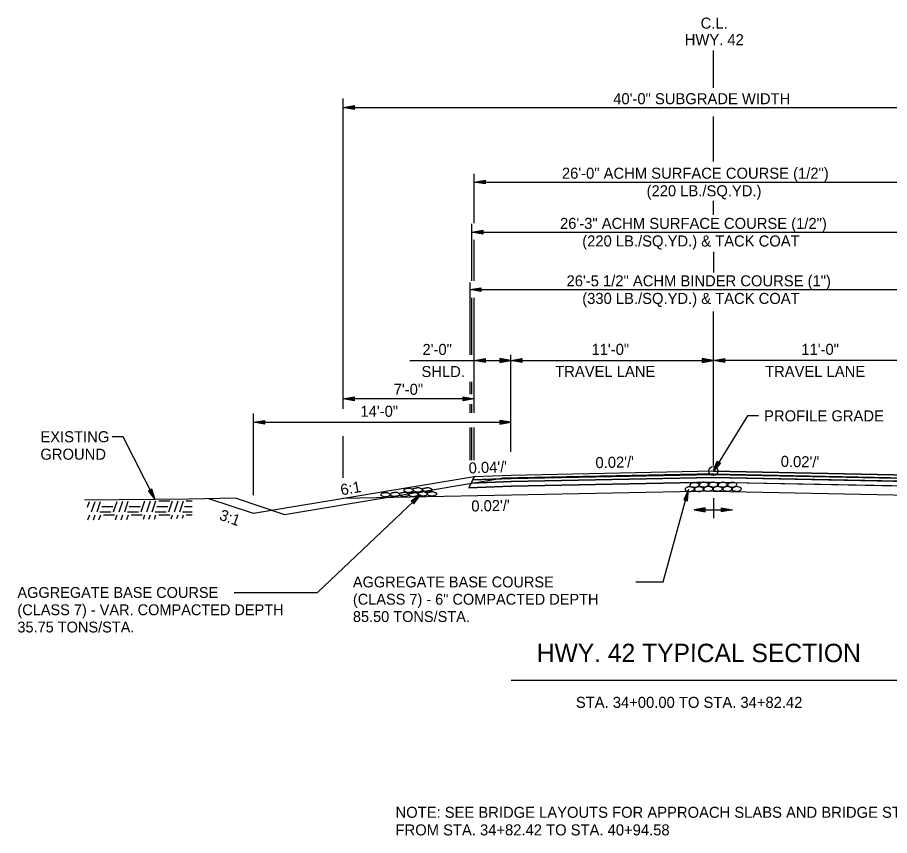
# Model space of a CAD drawing. Extents: x 1461570 to 1461697, y 1686711 to 1686957.
# Drawn here: x 1461574.47 to 1461621.86, y 1686717.78 to 1686762.26 of the extents above; entities that cross this region are included whole.
import ezdxf

# ---------------------------------------------------------------- set-up
doc = ezdxf.new("R2010")
doc.units = 0
for name, color, linetype in [('1', 7, 'Continuous'), ('10', 7, 'Continuous'), ('19', 7, 'Continuous'), ('20', 7, 'Continuous'), ('3', 7, 'Continuous'), ('42', 7, 'Continuous'), ('Default', 7, 'Continuous'), ('Level 1', 7, 'Continuous'), ('Level 9', 7, 'Continuous'), ('R_Draft', 7, 'Continuous'), ('R_Prop Surface', 7, 'Continuous')]:
    doc.layers.add(name, color=color, linetype=linetype)

# ---------------------------------------------------------------- blocks, each defined once
blk = doc.blocks.new('ROCKS')
at = {"layer": '1'}
blk.add_spline([(0.013, 0.06), (0.053, 0.053), (0.107, 0.033), (0.133, 0.013), (0.133, -0.007), (0.12, -0.033), (0.107, -0.04), (0.073, -0.053), (0.033, -0.067), (0.013, -0.067), (-0.02, -0.06), (-0.06, -0.053), (-0.087, -0.047), (-0.113, -0.02), (-0.113, -0.007), (-0.107, 0.02), (-0.087, 0.033), (-0.067, 0.047), (-0.033, 0.053), (-0.02, 0.06), (0.013, 0.06)], degree=3, dxfattribs=at)

msp = doc.modelspace()

# ---------------------------------------------------------------- linework, layer by layer
at = {"layer": '19'}
for p, q in [((1461592.17, 1686741.519), (1461592.77, 1686741.624)), ((1461592.77, 1686741.414), (1461592.17, 1686741.519)), ((1461592.33, 1686741.534), (1461592.77, 1686741.569)), ((1461592.77, 1686741.464), (1461592.33, 1686741.504)), ((1461592.77, 1686741.624), (1461592.77, 1686741.414)), ((1461598.685, 1686741.413), (1461598.685, 1686741.623)), ((1461598.685, 1686741.623), (1461599.285, 1686741.519)), ((1461598.685, 1686741.568), (1461599.125, 1686741.534)), ((1461599.285, 1686741.519), (1461598.685, 1686741.413)), ((1461599.125, 1686741.504), (1461598.685, 1686741.463)), ((1461612.275, 1686737.57), (1461612.498, 1686738.137)), ((1461612.676, 1686738.027), (1461612.275, 1686737.57)), ((1461612.348, 1686737.711), (1461612.541, 1686738.104)), ((1461612.635, 1686738.048), (1461612.371, 1686737.7)), ((1461612.498, 1686738.137), (1461612.676, 1686738.027)), ((1461612.285, 1686737.582), (1461601.285, 1686737.362)), ((1461612.285, 1686737.582), (1461601.285, 1686737.362)), ((1461612.285, 1686737.416), (1461601.29, 1686737.196)), ((1461612.285, 1686737.582), (1461623.285, 1686737.362)), ((1461623.285, 1686737.362), (1461612.285, 1686737.582)), ((1461612.285, 1686737.582), (1461623.285, 1686737.362)), ((1461612.285, 1686737.416), (1461622.202, 1686737.217)), ((1461612.285, 1686737.416), (1461612.285, 1686737.416)), ((1461612.285, 1686737.416), (1461612.285, 1686737.416)), ((1461612.285, 1686737.416), (1461623.28, 1686737.196)), ((1461599.285, 1686737.282), (1461587.285, 1686735.282)), ((1461599.285, 1686737.282), (1461598.991, 1686736.687)), ((1461599.117, 1686736.942), (1461598.991, 1686736.687)), ((1461599.201, 1686737.112), (1461599.117, 1686736.942)), ((1461599.285, 1686737.282), (1461599.201, 1686737.112)), ((1461612.285, 1686737.249), (1461601.295, 1686737.029)), ((1461612.285, 1686736.999), (1461601.303, 1686736.779)), ((1461612.285, 1686737.249), (1461612.285, 1686737.249)), ((1461612.285, 1686737.249), (1461612.285, 1686737.249)), ((1461612.285, 1686737.249), (1461623.275, 1686737.029)), ((1461612.285, 1686736.999), (1461612.285, 1686736.999)), ((1461612.285, 1686736.999), (1461623.268, 1686736.779)), ((1461612.285, 1686736.499), (1461592.17, 1686736.097)), ((1461609.564, 1686731.575), (1461610.941, 1686736.585)), ((1461610.941, 1686736.585), (1461610.685, 1686736.032)), ((1461610.887, 1686735.98), (1461610.941, 1686736.585)), ((1461612.285, 1686736.499), (1461632.401, 1686736.097)), ((1461587.285, 1686735.282), (1461584.872, 1686736.087)), ((1461590.775, 1686730.998), (1461596.374, 1686736.296)), ((1461596.375, 1686736.3), (1461595.867, 1686735.965)), ((1461596.251, 1686736.2), (1461595.905, 1686735.928)), ((1461595.977, 1686735.85), (1461596.271, 1686736.179)), ((1461596.011, 1686735.814), (1461596.375, 1686736.3)), ((1461610.685, 1686736.032), (1461610.887, 1686735.98)), ((1461610.888, 1686736.434), (1461610.737, 1686736.022)), ((1461610.839, 1686735.993), (1461610.915, 1686736.427)), ((1461595.867, 1686735.965), (1461596.011, 1686735.814)), ((1461608.066, 1686731.575), (1461609.564, 1686731.575)), ((1461586.24, 1686730.998), (1461590.775, 1686730.998))]:
    msp.add_line(p, q, dxfattribs=at)
for points in [[(1461614.743, 1686740.596), (1461614.143, 1686740.596), (1461612.275, 1686737.571)], [(1461612.285, 1686737.582), (1461601.285, 1686737.362)], [(1461612.285, 1686737.416), (1461601.29, 1686737.196)], [(1461602.202, 1686737.214), (1461612.285, 1686737.416)], [(1461612.285, 1686737.249), (1461623.275, 1686737.029), (1461625.454, 1686736.942), (1461625.37, 1686737.112), (1461623.28, 1686737.196), (1461612.285, 1686737.416)], [(1461612.285, 1686737.416), (1461612.285, 1686737.416)], [(1461598.991, 1686736.687), (1461601.303, 1686736.779), (1461612.285, 1686736.999)], [(1461599.117, 1686736.942), (1461601.295, 1686737.029), (1461612.285, 1686737.249)], [(1461612.285, 1686737.249), (1461601.295, 1686737.029), (1461599.117, 1686736.942)], [(1461599.201, 1686737.112), (1461601.29, 1686737.196), (1461601.29, 1686737.196)], [(1461601.29, 1686737.196), (1461599.201, 1686737.112)], [(1461601.285, 1686737.362), (1461599.285, 1686737.282)], [(1461601.29, 1686737.196), (1461602.202, 1686737.214)], [(1461612.285, 1686737.249), (1461612.285, 1686737.249)], [(1461612.285, 1686737.249), (1461612.285, 1686737.249)], [(1461612.285, 1686737.249), (1461612.285, 1686737.249), (1461612.285, 1686737.249)], [(1461612.285, 1686736.999), (1461623.268, 1686736.779), (1461625.58, 1686736.687), (1461625.454, 1686736.942), (1461623.275, 1686737.029), (1461612.285, 1686737.249)]]:
    msp.add_lwpolyline(points, dxfattribs=at)
at = {"layer": '20'}
for p, q in [((1461592.17, 1686740.986), (1461592.17, 1686757.853)), ((1461592.17, 1686757.365), (1461592.77, 1686757.47)), ((1461592.17, 1686757.365), (1461632.401, 1686757.365)), ((1461592.77, 1686757.26), (1461592.17, 1686757.365)), ((1461592.33, 1686757.38), (1461592.77, 1686757.415)), ((1461592.77, 1686757.31), (1461592.33, 1686757.35)), ((1461592.77, 1686757.47), (1461592.77, 1686757.26)), ((1461592.17, 1686750.799), (1461592.17, 1686756.936)), ((1461599.285, 1686751.078), (1461599.285, 1686753.762)), ((1461599.285, 1686753.31), (1461599.885, 1686753.415)), ((1461599.285, 1686753.31), (1461625.285, 1686753.31)), ((1461599.885, 1686753.205), (1461599.285, 1686753.31)), ((1461599.445, 1686753.325), (1461599.885, 1686753.36)), ((1461599.885, 1686753.255), (1461599.445, 1686753.295)), ((1461599.885, 1686753.415), (1461599.885, 1686753.205)), ((1461599.159, 1686747.93), (1461599.159, 1686751.035)), ((1461599.159, 1686750.582), (1461599.759, 1686750.687)), ((1461599.759, 1686750.687), (1461599.759, 1686750.477)), ((1461599.159, 1686750.582), (1461625.412, 1686750.582)), ((1461599.759, 1686750.477), (1461599.159, 1686750.582)), ((1461599.319, 1686750.597), (1461599.759, 1686750.632)), ((1461599.759, 1686750.527), (1461599.319, 1686750.567)), ((1461599.285, 1686747.93), (1461599.285, 1686750.162)), ((1461599.054, 1686747.845), (1461599.054, 1686743.909)), ((1461599.054, 1686747.459), (1461599.654, 1686747.564)), ((1461599.054, 1686747.459), (1461625.517, 1686747.459)), ((1461599.654, 1686747.354), (1461599.054, 1686747.459)), ((1461599.214, 1686747.474), (1461599.654, 1686747.509)), ((1461599.654, 1686747.404), (1461599.214, 1686747.444)), ((1461599.654, 1686747.564), (1461599.654, 1686747.354)), ((1461599.159, 1686743.909), (1461599.159, 1686747.013)), ((1461599.285, 1686743.909), (1461599.285, 1686747.013)), ((1461599.285, 1686740.759), (1461599.285, 1686743.931)), ((1461599.285, 1686743.607), (1461599.885, 1686743.712)), ((1461599.885, 1686743.502), (1461599.285, 1686743.607)), ((1461599.445, 1686743.622), (1461599.885, 1686743.657)), ((1461599.885, 1686743.552), (1461599.445, 1686743.592)), ((1461599.885, 1686743.712), (1461599.885, 1686743.502)), ((1461600.685, 1686743.712), (1461600.685, 1686743.502)), ((1461601.285, 1686743.607), (1461600.685, 1686743.712)), ((1461601.125, 1686743.622), (1461600.685, 1686743.657)), ((1461600.685, 1686743.502), (1461601.285, 1686743.607)), ((1461600.685, 1686743.552), (1461601.125, 1686743.592)), ((1461601.285, 1686738.638), (1461601.285, 1686743.906)), ((1461601.285, 1686743.607), (1461601.885, 1686743.712)), ((1461601.885, 1686743.502), (1461601.285, 1686743.607)), ((1461601.445, 1686743.622), (1461601.885, 1686743.657)), ((1461601.885, 1686743.552), (1461601.445, 1686743.592)), ((1461601.885, 1686743.712), (1461601.885, 1686743.502)), ((1461611.685, 1686743.713), (1461611.685, 1686743.503)), ((1461612.285, 1686743.608), (1461611.685, 1686743.713)), ((1461612.125, 1686743.623), (1461611.685, 1686743.658)), ((1461611.685, 1686743.503), (1461612.285, 1686743.608)), ((1461611.685, 1686743.553), (1461612.125, 1686743.593)), ((1461612.285, 1686743.608), (1461612.885, 1686743.713)), ((1461612.885, 1686743.503), (1461612.285, 1686743.608)), ((1461612.445, 1686743.623), (1461612.885, 1686743.658)), ((1461612.885, 1686743.553), (1461612.445, 1686743.593)), ((1461612.885, 1686743.713), (1461612.885, 1686743.503)), ((1461599.054, 1686742.455), (1461599.054, 1686741.775)), ((1461599.159, 1686741.775), (1461599.159, 1686742.455)), ((1461599.054, 1686741.238), (1461599.054, 1686740.759)), ((1461599.159, 1686740.759), (1461599.159, 1686741.238)), ((1461587.285, 1686736.283), (1461587.285, 1686740.719)), ((1461587.285, 1686740.246), (1461587.885, 1686740.352)), ((1461587.885, 1686740.142), (1461587.285, 1686740.246)), ((1461587.445, 1686740.262), (1461587.885, 1686740.297)), ((1461587.885, 1686740.352), (1461587.885, 1686740.142)), ((1461600.685, 1686740.352), (1461600.685, 1686740.142)), ((1461601.285, 1686740.246), (1461600.685, 1686740.352)), ((1461601.125, 1686740.262), (1461600.685, 1686740.297)), ((1461600.685, 1686740.142), (1461601.285, 1686740.246)), ((1461587.885, 1686740.192), (1461587.445, 1686740.232)), ((1461599.054, 1686739.969), (1461599.054, 1686738.191)), ((1461599.159, 1686738.191), (1461599.159, 1686739.969)), ((1461599.285, 1686738.191), (1461599.285, 1686739.969)), ((1461600.685, 1686740.192), (1461601.125, 1686740.232)), ((1461592.17, 1686737.224), (1461592.17, 1686739.484)), ((1461581.771, 1686736.606), (1461581.583, 1686736.511)), ((1461581.583, 1686736.511), (1461581.947, 1686736.023)), ((1461581.628, 1686736.534), (1461581.862, 1686736.159)), ((1461581.888, 1686736.172), (1461581.722, 1686736.581)), ((1461581.947, 1686736.023), (1461581.771, 1686736.606))]:
    msp.add_line(p, q, dxfattribs=at)
msp.add_lwpolyline([(1461581.947, 1686736.023), (1461580.217, 1686739.462), (1461579.617, 1686739.462)], dxfattribs=at)
at = {"layer": '3'}
msp.add_line((1461601.3, 1686726.22), (1461623.3, 1686726.22), dxfattribs=at)
at = {"layer": '42'}
for p, q in [((1461612.285, 1686758.427), (1461612.285, 1686760.458)), ((1461612.285, 1686754.424), (1461612.285, 1686756.866)), ((1461612.285, 1686751.526), (1461612.285, 1686752.291)), ((1461612.285, 1686749.511), (1461612.285, 1686748.39)), ((1461612.285, 1686737.903), (1461612.285, 1686746.266)), ((1461595.781, 1686743.607), (1461600.291, 1686743.607)), ((1461600.285, 1686743.607), (1461612.285, 1686743.608)), ((1461624.285, 1686743.606), (1461612.285, 1686743.607)), ((1461587.285, 1686740.246), (1461601.285, 1686740.246)), ((1461581.193, 1686735.374), (1461581.393, 1686735.974)), ((1461581.493, 1686735.374), (1461581.693, 1686735.974)), ((1461581.793, 1686735.374), (1461581.993, 1686735.974)), ((1461582.143, 1686735.974), (1461582.743, 1686735.974)), ((1461582.693, 1686735.374), (1461582.893, 1686735.974)), ((1461582.993, 1686735.374), (1461583.193, 1686735.974)), ((1461583.293, 1686735.374), (1461583.493, 1686735.974)), ((1461583.643, 1686735.974), (1461583.953, 1686735.974)), ((1461612.285, 1686736.119), (1461612.285, 1686735.032)), ((1461578.279, 1686735.634), (1461578.381, 1686735.94)), ((1461578.493, 1686735.374), (1461578.681, 1686735.938)), ((1461578.793, 1686735.374), (1461578.98, 1686735.936)), ((1461579.043, 1686735.674), (1461579.643, 1686735.674)), ((1461579.693, 1686735.374), (1461579.883, 1686735.945)), ((1461579.993, 1686735.374), (1461580.185, 1686735.952)), ((1461580.293, 1686735.374), (1461580.487, 1686735.958)), ((1461580.543, 1686735.674), (1461581.143, 1686735.674)), ((1461582.043, 1686735.674), (1461582.643, 1686735.674)), ((1461583.543, 1686735.674), (1461583.953, 1686735.674)), ((1461611.838, 1686735.589), (1461611.238, 1686735.484)), ((1461611.838, 1686735.534), (1461611.398, 1686735.499)), ((1461611.838, 1686735.379), (1461611.838, 1686735.589)), ((1461612.733, 1686735.379), (1461612.733, 1686735.589)), ((1461612.733, 1686735.589), (1461613.333, 1686735.484)), ((1461612.733, 1686735.534), (1461613.173, 1686735.499)), ((1461578.298, 1686734.941), (1461578.393, 1686735.224)), ((1461578.598, 1686734.939), (1461578.693, 1686735.224)), ((1461578.897, 1686734.936), (1461578.993, 1686735.224)), ((1461578.943, 1686735.374), (1461579.543, 1686735.374)), ((1461579.143, 1686735.224), (1461579.743, 1686735.224)), ((1461579.799, 1686734.944), (1461579.893, 1686735.224)), ((1461580.101, 1686734.95), (1461580.193, 1686735.224)), ((1461580.403, 1686734.956), (1461580.493, 1686735.224)), ((1461580.443, 1686735.374), (1461581.043, 1686735.374)), ((1461580.643, 1686735.224), (1461581.193, 1686735.224)), ((1461581.193, 1686735.224), (1461581.243, 1686735.224)), ((1461581.31, 1686734.975), (1461581.393, 1686735.224)), ((1461581.612, 1686734.981), (1461581.693, 1686735.224)), ((1461581.914, 1686734.987), (1461581.993, 1686735.224)), ((1461581.943, 1686735.374), (1461582.543, 1686735.374)), ((1461582.143, 1686735.224), (1461582.743, 1686735.224)), ((1461582.82, 1686735.006), (1461582.893, 1686735.224)), ((1461583.123, 1686735.016), (1461583.193, 1686735.224)), ((1461583.429, 1686735.034), (1461583.493, 1686735.224)), ((1461583.443, 1686735.374), (1461583.953, 1686735.374)), ((1461583.643, 1686735.224), (1461583.953, 1686735.224)), ((1461611.238, 1686735.484), (1461611.838, 1686735.379)), ((1461611.238, 1686735.484), (1461613.333, 1686735.484)), ((1461611.398, 1686735.469), (1461611.838, 1686735.429)), ((1461613.333, 1686735.484), (1461612.733, 1686735.379)), ((1461613.173, 1686735.469), (1461612.733, 1686735.429))]:
    msp.add_line(p, q, dxfattribs=at)
msp.add_circle((1461612.284, 1686737.601), 0.25, dxfattribs=at)
at = {"layer": 'Level 9'}
msp.add_line((1461599.285, 1686741.519), (1461592.17, 1686741.519), dxfattribs=at)
at = {"layer": 'R_Draft'}
for p, q in [((1461612.285, 1686737.437), (1461600.785, 1686737.207)), ((1461612.285, 1686737.437), (1461622.785, 1686737.227)), ((1461588.984, 1686735.24), (1461600.785, 1686737.207)), ((1461586.351, 1686736.117), (1461588.984, 1686735.24))]:
    msp.add_line(p, q, dxfattribs=at)
msp.add_lwpolyline([(1461586.351, 1686736.117), (1461583.753, 1686736.064), (1461578.109, 1686736.006)], dxfattribs=at)
at = {"layer": 'R_Prop Surface'}
for p, q in [((1461601.295, 1686737.029), (1461599.117, 1686736.942)), ((1461601.29, 1686737.196), (1461599.201, 1686737.112)), ((1461601.285, 1686737.362), (1461599.285, 1686737.282)), ((1461601.285, 1686737.362), (1461599.285, 1686737.282)), ((1461601.303, 1686736.779), (1461598.991, 1686736.687))]:
    msp.add_line(p, q, dxfattribs=at)

# ---------------------------------------------------------------- block references
at = {"layer": '1', "xscale": 1.968733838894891, "yscale": -1.968733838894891}
for p in [(1461594.972, 1686736.319), (1461595.471, 1686736.319), (1461595.704, 1686736.542), (1461595.966, 1686736.319), (1461596.202, 1686736.568), (1461596.478, 1686736.345), (1461596.727, 1686736.568), (1461596.977, 1686736.345), (1461594.447, 1686736.306)]:
    msp.add_blockref('ROCKS', p, dxfattribs=at)
at = {"layer": 'Level 1', "xscale": 2.011654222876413, "yscale": 2.011654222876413, "rotation": 1.8263814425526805}
for p in [(1461611.241, 1686736.845), (1461611.75, 1686736.862), (1461612.26, 1686736.863), (1461612.776, 1686736.859), (1461613.291, 1686736.856), (1461610.981, 1686736.618), (1461611.486, 1686736.617), (1461611.995, 1686736.633), (1461612.505, 1686736.634), (1461613.021, 1686736.631), (1461613.536, 1686736.627)]:
    msp.add_blockref('ROCKS', p, dxfattribs=at)

# ---------------------------------------------------------------- texts
at = {"layer": '1'}
for s, p in [('NOTE: SEE BRIDGE LAYOUTS FOR APPROACH SLABS AND BRIDGE STRUCTURES ', (1461595.012, 1686718.744)), ('FROM STA. 34+82.42 TO STA. 40+94.58', (1461595.012, 1686717.788))]:
    msp.add_text(s, height=0.6, dxfattribs=at).set_placement(p)
at = {"layer": '10'}
for s, p in [('EXISTING', (1461575.712, 1686739.162)), ('GROUND', (1461575.712, 1686738.212))]:
    msp.add_text(s, height=0.6, dxfattribs=at).set_placement(p)
at = {"layer": '19'}
for s, height, rotation, p in [('2\'-0"', 0.6, 360, (1461596.477, 1686743.907)), ('11\'-0"', 0.6, 360, (1461605.663, 1686743.913)), ('SHLD.', 0.6, 360, (1461596.423, 1686742.707)), ('TRAVEL LANE', 0.6, 360, (1461603.69, 1686742.713)), ('14\'-0"', 0.6, 360, (1461593.106, 1686740.546)), ('PROFILE GRADE', 0.6, 360, (1461615.043, 1686740.296)), ("0.02'/'", 0.6, 1.1458, (1461605.885, 1686737.754)), ("0.02'/'", 0.6, 358.8542, (1461615.941, 1686737.829)), ("0.04'/'", 0.6, 2.1602, (1461598.996, 1686737.461)), ('6:1', 0.6, 9.8416, (1461592.075, 1686736.271)), ("0.02'/'", 0.6, 1.1458, (1461599.135, 1686735.395)), ('3:1', 0.6, 340.4943, (1461585.392, 1686734.968)), ('AGGREGATE BASE COURSE', 0.59001, 360, (1461592.696, 1686731.271)), ('AGGREGATE BASE COURSE', 0.59001, 360, (1461574.464, 1686730.7)), ('(CLASS 7) - 6" COMPACTED DEPTH', 0.59001, 360, (1461592.696, 1686730.331)), ('(CLASS 7) - VAR. COMPACTED DEPTH', 0.59001, 360, (1461574.464, 1686729.76)), ('85.50 TONS/STA.', 0.59001, 360, (1461592.696, 1686729.391)), ('35.75 TONS/STA.', 0.59001, 360, (1461574.464, 1686728.82)), ('HWY. 42 TYPICAL SECTION', 1, 359.9954, (1461602.689, 1686727.209)), ('STA. 34+00.00 TO STA. 34+82.42', 0.6, 359.9954, (1461604.813, 1686724.722))]:
    msp.add_text(s, height=height, rotation=rotation, dxfattribs=at).set_placement(p)
for s, p in [('11\'-0"', (1461617.065, 1686743.913)), ('TRAVEL LANE', (1461615.093, 1686742.713)), ('7\'-0"', (1461594.913, 1686741.741))]:
    msp.add_text(s, height=0.6, dxfattribs=at).set_placement(p)
at = {"layer": 'Default'}
for s, p in [('40\'-0" SUBGRADE WIDTH', (1461606.843, 1686757.539)), ('26\'-0" ACHM SURFACE COURSE (1/2")', (1461604.054, 1686753.488)), ('(220 LB./SQ.YD.)', (1461608.656, 1686752.532)), ('26\'-3" ACHM SURFACE COURSE (1/2")', (1461603.951, 1686750.76)), ('(220 LB./SQ.YD.) & TACK COAT', (1461605.159, 1686749.804)), ('26\'-5 1/2" ACHM BINDER COURSE (1")', (1461604.306, 1686747.637)), ('(330 LB./SQ.YD.) & TACK COAT', (1461605.159, 1686746.681))]:
    msp.add_text(s, height=0.60001, dxfattribs=at).set_placement(p)
at = {"layer": 'R_Draft'}
for s, p in [('C.L.', (1461611.593, 1686761.648)), ('HWY. 42', (1461610.729, 1686760.748))]:
    msp.add_text(s, height=0.6, rotation=360, dxfattribs=at).set_placement(p)

doc.saveas('drawing.dxf')
